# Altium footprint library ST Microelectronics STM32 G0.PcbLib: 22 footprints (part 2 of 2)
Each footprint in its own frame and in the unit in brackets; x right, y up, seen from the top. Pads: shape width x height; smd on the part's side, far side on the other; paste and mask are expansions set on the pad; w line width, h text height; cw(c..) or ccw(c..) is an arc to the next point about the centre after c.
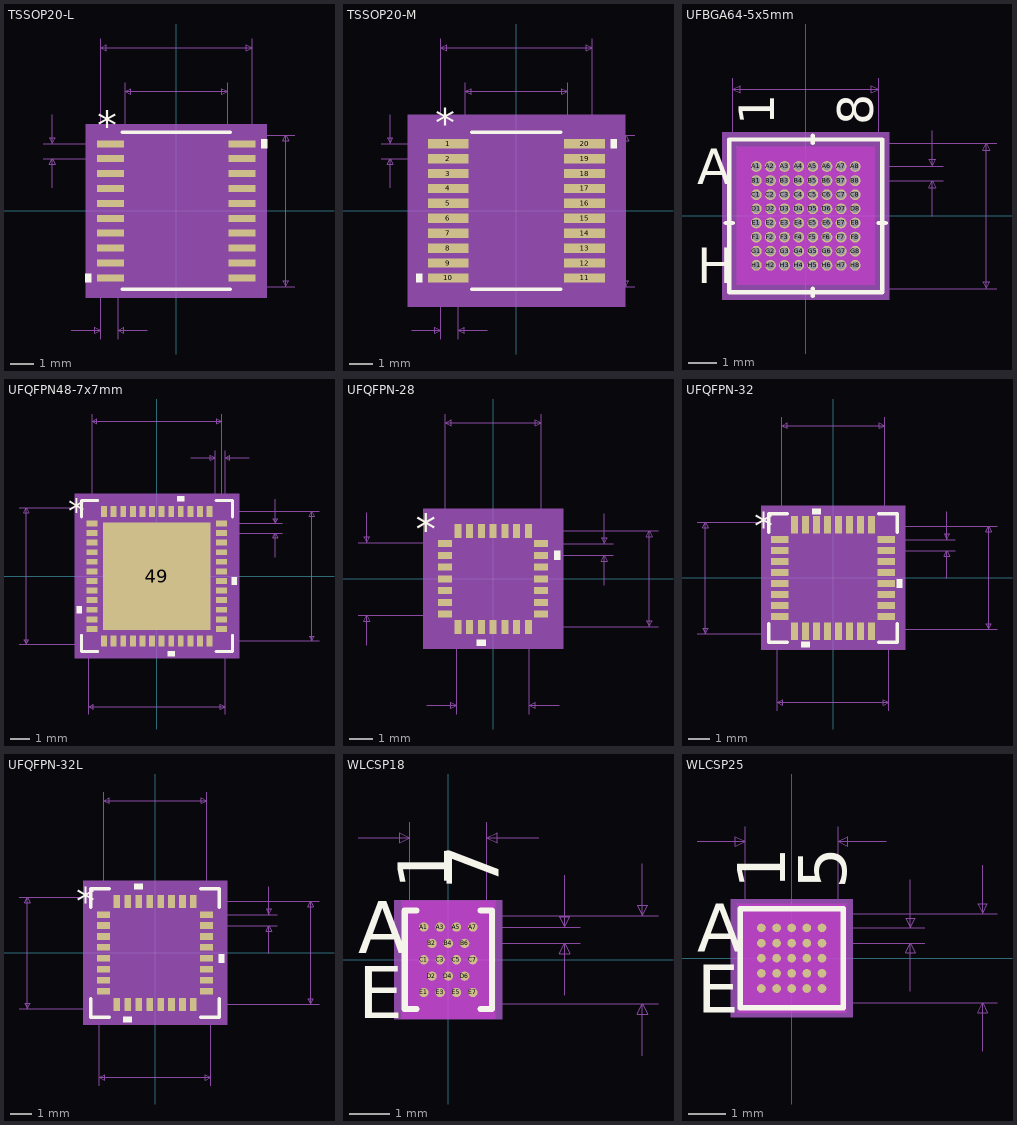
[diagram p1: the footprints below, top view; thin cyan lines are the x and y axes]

## TSSOP20-L [mil] "STM32 package, TSSOP20, 6.4 x 4.4mm"
pads (20):
  rect 46x12 smd paste+0 mask+0: 1(-113,115.16) 2(-113,89.57) 3(-113,63.98) 4(-113,38.39) 5(-113,12.8) 6(-113,-12.8) 7(-113,-38.39) 8(-113,-63.98) 9(-113,-89.57) 10(-113,-115.16) 11(113,-115.16) 12(113,-89.57) 13(113,-63.98) 14(113,-38.39) 15(113,-12.8) 16(113,12.8) 17(113,38.39) 18(113,63.98) 19(113,89.57) 20(113,115.16)
Top Overlay:
  region: 146,122.66 156,122.66 156,107.66 146,107.66
  region: -146,-107.66 -156,-107.66 -156,-122.66 -146,-122.66
  lines w6: -93,-135 93,-135 ; -93,135 93,135
  text "*" at -135.5,122.16 h50
Mechanical 5:
  region: 155,-149 -155,-149 -155,149 155,149
Mechanical 7:
  lines w1: -228,89.57 -113,89.57 ; -228,115.16 -113,115.16 ; -213,39.57 -213,89.57 ; -213,165.16 -213,115.16 ; -180,-205 -130,-205 ; -130,-220 -130,0 -130,295 ; -100,-220 -100,0 ; -88,0 -88,220 ; -50,-205 -100,-205 ; 0,-130 203,-130 ; 0,130 203,130 ; 88,0 88,220 ; 130,0 130,295 ; -213,89.57 -208,79.57 -218,79.57 -213,89.57 ; -213,115.16 -208,125.16 -218,125.16 -213,115.16 ; -130,-205 -140,-210 -140,-200 -130,-205 ; -130,280 -120,275 -120,285 -130,280 ; -130,280 130,280 ; -100,-205 -90,-210 -90,-200 -100,-205 ; -88,205 -78,200 -78,210 -88,205 ; -88,205 88,205 ; 88,205 78,200 78,210 88,205 ; 130,280 120,275 120,285 130,280 ; 188,-130 193,-120 183,-120 188,-130 ; 188,-130 188,130 ; 188,130 193,120 183,120 188,130
  text "0.03in/0.762mm" at -202.5,-250 h25
  text "0.026in/0.65mm" at -408,89.86 h25
  text "0.26in/6.604mm" at 208,-12.5 h25
  text "0.26in/6.604mm" at -87.5,300 h25
  text "0.176in/4.47mm" at -87.5,225 h25
  text "Alt 2 Padstyle: OX90Y60D30P" at -337.5,-630 h50
  text "Alt 1 Padstyle: OX60Y90D30P" at -337.5,-570 h50
  text "Pin One Padstyle: RX46Y12D0T" at -350,-390 h50
  text "Default Padstyle: RX46Y12D0T" at -350,-330 h50
Mechanical 13:
  lines w0: -12,130 ccw(c0,130) 12,130
  lines w1: -130,-121.16 -88,-121.16 -88,-109.16 -130,-109.16 -130,-121.16 ; -130,-95.57 -88,-95.57 -88,-83.57 -130,-83.57 -130,-95.57 ; -130,-69.98 -88,-69.98 -88,-57.98 -130,-57.98 -130,-69.98 ; -130,-44.39 -88,-44.39 -88,-32.39 -130,-32.39 -130,-44.39 ; -130,-18.8 -88,-18.8 -88,-6.8 -130,-6.8 -130,-18.8 ; -130,6.8 -88,6.8 -88,18.8 -130,18.8 -130,6.8 ; -130,32.39 -88,32.39 -88,44.39 -130,44.39 -130,32.39 ; -130,57.98 -88,57.98 -88,69.98 -130,69.98 -130,57.98 ; -130,83.57 -88,83.57 -88,95.57 -130,95.57 -130,83.57 ; -130,109.16 -88,109.16 -88,121.16 -130,121.16 -130,109.16 ; -88,-130 -88,130 88,130 88,-130 -88,-130 ; 88,-121.16 130,-121.16 130,-109.16 88,-109.16 88,-121.16 ; 88,-95.57 130,-95.57 130,-83.57 88,-83.57 88,-95.57 ; 88,-69.98 130,-69.98 130,-57.98 88,-57.98 88,-69.98 ; 88,-44.39 130,-44.39 130,-32.39 88,-32.39 88,-44.39 ; 88,-18.8 130,-18.8 130,-6.8 88,-6.8 88,-18.8 ; 88,6.8 130,6.8 130,18.8 88,18.8 88,6.8 ; 88,32.39 130,32.39 130,44.39 88,44.39 88,32.39 ; 88,57.98 130,57.98 130,69.98 88,69.98 88,57.98 ; 88,83.57 130,83.57 130,95.57 88,95.57 88,83.57 ; 88,109.16 130,109.16 130,121.16 88,121.16 88,109.16
  text "*" at -85.5,77 h50
Mechanical 15:
  region: -92,-125.16 -140,-125.16 -140,125.16 -92,125.16 -92,134 92,134 92,125.16 140,125.16 140,-125.16 92,-125.16 92,-134 -92,-134
  lines w6: -140,-125.16 -92,-125.16 -92,-134 92,-134 92,-125.16 140,-125.16 140,125.16 92,125.16 92,134 -92,134 -92,125.16 -140,125.16 -140,-125.16
3D body "TSSOP20-L.step": height 47.09, standoff 0, extent -129.99,-129.99 130.01,130.01
3D body: height 10, standoff 0, extent 0,0 10,10

## TSSOP20-M [mil] "STM32 package, TSSOP20, 6.4 x 4.4mm"
pads (20):
  rect 70x16 smd paste+0 mask+0: 1(-117,115.16) 2(-117,89.57) 3(-117,63.98) 4(-117,38.39) 5(-117,12.8) 6(-117,-12.8) 7(-117,-38.39) 8(-117,-63.98) 9(-117,-89.57) 10(-117,-115.16) 11(117,-115.16) 12(117,-89.57) 13(117,-63.98) 14(117,-38.39) 15(117,-12.8) 16(117,12.8) 17(117,38.39) 18(117,63.98) 19(117,89.57) 20(117,115.16)
Top Overlay:
  region: -162,-107.66 -172,-107.66 -172,-122.66 -162,-122.66
  region: 162,122.66 172,122.66 172,107.66 162,107.66
  lines w6: -76.4,-135 76.4,-135 ; -76.4,135 76.4,135
  text "*" at -139.5,126.16 h50
Mechanical 5:
  region: 187,-165 -187,-165 -187,165 187,165
Mechanical 7:
  lines w1: -232,89.57 -117,89.57 ; -232,115.16 -117,115.16 ; -217,39.57 -217,89.57 ; -217,165.16 -217,115.16 ; -180,-205 -130,-205 ; -130,-220 -130,0 -130,295 ; -100,-220 -100,0 ; -88,0 -88,220 ; -50,-205 -100,-205 ; 0,-130 203,-130 ; 0,130 203,130 ; 88,0 88,220 ; 130,0 130,295 ; -217,89.57 -222,79.57 -212,79.57 -217,89.57 ; -217,115.16 -222,125.16 -212,125.16 -217,115.16 ; -130,-205 -140,-200 -140,-210 -130,-205 ; -130,280 130,280 ; -130,280 -120,285 -120,275 -130,280 ; -100,-205 -90,-200 -90,-210 -100,-205 ; -88,205 88,205 ; -88,205 -78,210 -78,200 -88,205 ; 88,205 78,210 78,200 88,205 ; 130,280 120,285 120,275 130,280 ; 188,-130 188,130 ; 188,-130 183,-120 193,-120 188,-130 ; 188,130 183,120 193,120 188,130
  text "Default Padstyle: RX70Y16D0T" at -350,-330 h50
  text "Pin One Padstyle: RX70Y16D0T" at -350,-390 h50
  text "Alt 1 Padstyle: OX60Y90D30P" at -337.5,-570 h50
  text "Alt 2 Padstyle: OX90Y60D30P" at -337.5,-630 h50
  text "0.176in/4.47mm" at -87.5,225 h25
  text "0.26in/6.604mm" at -87.5,300 h25
  text "0.26in/6.604mm" at 208,-12.5 h25
  text "0.026in/0.65mm" at -412,89.86 h25
  text "0.03in/0.762mm" at -202.5,-250 h25
Mechanical 13:
  lines w0: -12,130 ccw(c0,130) 12,130
  lines w1: -130,-121.16 -130,-109.16 -88,-109.16 -88,-121.16 -130,-121.16 ; -130,-95.57 -130,-83.57 -88,-83.57 -88,-95.57 -130,-95.57 ; -130,-69.98 -130,-57.98 -88,-57.98 -88,-69.98 -130,-69.98 ; -130,-44.39 -130,-32.39 -88,-32.39 -88,-44.39 -130,-44.39 ; -130,-18.8 -130,-6.8 -88,-6.8 -88,-18.8 -130,-18.8 ; -130,6.8 -130,18.8 -88,18.8 -88,6.8 -130,6.8 ; -130,32.39 -130,44.39 -88,44.39 -88,32.39 -130,32.39 ; -130,57.98 -130,69.98 -88,69.98 -88,57.98 -130,57.98 ; -130,83.57 -130,95.57 -88,95.57 -88,83.57 -130,83.57 ; -130,109.16 -130,121.16 -88,121.16 -88,109.16 -130,109.16 ; -88,-130 88,-130 88,130 -88,130 -88,-130 ; 88,-121.16 88,-109.16 130,-109.16 130,-121.16 88,-121.16 ; 88,-95.57 88,-83.57 130,-83.57 130,-95.57 88,-95.57 ; 88,-69.98 88,-57.98 130,-57.98 130,-69.98 88,-69.98 ; 88,-44.39 88,-32.39 130,-32.39 130,-44.39 88,-44.39 ; 88,-18.8 88,-6.8 130,-6.8 130,-18.8 88,-18.8 ; 88,6.8 88,18.8 130,18.8 130,6.8 88,6.8 ; 88,32.39 88,44.39 130,44.39 130,32.39 88,32.39 ; 88,57.98 88,69.98 130,69.98 130,57.98 88,57.98 ; 88,83.57 88,95.57 130,95.57 130,83.57 88,83.57 ; 88,109.16 88,121.16 130,121.16 130,109.16 88,109.16
  text "*" at -85.5,77 h50
Mechanical 15:
  region: -108,-143.16 -172,-143.16 -172,143.16 -108,143.16 -108,150 108,150 108,143.16 172,143.16 172,-143.16 108,-143.16 108,-150 -108,-150
  lines w6: -172,-143.16 -172,143.16 -108,143.16 -108,150 108,150 108,143.16 172,143.16 172,-143.16 108,-143.16 108,-150 -108,-150 -108,-143.16 -172,-143.16
3D body: height 10, standoff 0, extent 0,0 10,10
3D body "TSSOP20-M.step": height 47.09, standoff 0, extent -129.99,-129.99 130.01,130.01

## UFBGA64-5x5mm [mil] "STM32 package, UFBGA64, 5 x 5mm"
pads (64):
  round 15 hole 11 mask+0: A1(-68.9,68.9) A2(-49.21,68.9) A3(-29.53,68.9) A4(-9.84,68.9) A5(9.84,68.9) A6(29.53,68.9) A7(49.21,68.9) A8(68.9,68.9) B1(-68.9,49.21) B2(-49.21,49.21) B3(-29.53,49.21) B4(-9.84,49.21) B5(9.84,49.21) B6(29.53,49.21) B7(49.21,49.21) B8(68.9,49.21) C1(-68.9,29.53) C2(-49.21,29.53) C3(-29.53,29.53) C4(-9.84,29.53) C5(9.84,29.53) C6(29.53,29.53) C7(49.21,29.53) C8(68.9,29.53) D1(-68.9,9.84) D2(-49.21,9.84) D3(-29.53,9.84) D4(-9.84,9.84) D5(9.84,9.84) D6(29.53,9.84) D7(49.21,9.84) D8(68.9,9.84) E1(-68.9,-9.84) E2(-49.21,-9.84) E3(-29.53,-9.84) E4(-9.84,-9.84) E5(9.84,-9.84) E6(29.53,-9.84) E7(49.21,-9.84) E8(68.9,-9.84) F1(-68.9,-29.53) F2(-49.21,-29.53) F3(-29.53,-29.53) F4(-9.84,-29.53) F5(9.84,-29.53) F6(29.53,-29.53) F7(49.21,-29.53) F8(68.9,-29.53) G1(-68.9,-49.21) G2(-49.21,-49.21) G3(-29.53,-49.21) G4(-9.84,-49.21) G5(9.84,-49.21) G6(29.53,-49.21) G7(49.21,-49.21) G8(68.9,-49.21) H1(-68.9,-68.9) H2(-49.21,-68.9) H3(-29.53,-68.9) H4(-9.84,-68.9) H5(9.84,-68.9) H6(29.53,-68.9) H7(49.21,-68.9) H8(68.9,-68.9)
Top Overlay:
  lines w6: -111.5,-9.84 -101.5,-9.84 ; 9.84,-111.5 9.84,-101.5 ; 9.84,101.5 9.84,111.5 ; 101.5,-9.84 111.5,-9.84 ; -106.5,-106.5 -106.5,106.5 106.5,106.5 106.5,-106.5 -106.5,-106.5
  text "8" at 93.9,126.5 h50
  text "1" at -43.9,126.5 h50
  text "H" at -151.5,-93.9 h50
  text "A" at -151.5,43.9 h50
Bottom Overlay:
  text "8" at 43.9,126.5 h50
  text "1" at -93.9,126.5 h50
  text "H" at -126.5,-93.9 h50
  text "A" at -126.5,43.9 h50
Keep-Out Layer:
  region: -96.24,-96.24 -96.24,96.24 96.24,96.24 96.24,-96.24
Mechanical 5:
  region: 116.5,-116.5 -116.5,-116.5 -116.5,116.5 116.5,116.5
Mechanical 7:
  lines w1: -101.5,0 -101.5,191.5 ; 0,-101.5 266.5,-101.5 ; 0,101.5 266.5,101.5 ; 68.9,49.21 191.5,49.21 ; 68.9,68.9 191.5,68.9 ; 101.5,0 101.5,191.5 ; 176.5,-0.79 176.5,49.21 ; 176.5,118.9 176.5,68.9 ; -101.5,176.5 -91.5,171.5 -91.5,181.5 -101.5,176.5 ; -101.5,176.5 101.5,176.5 ; 101.5,176.5 91.5,171.5 91.5,181.5 101.5,176.5 ; 176.5,49.21 181.5,39.21 171.5,39.21 176.5,49.21 ; 176.5,68.9 181.5,78.9 171.5,78.9 176.5,68.9 ; 251.5,-101.5 256.5,-91.5 246.5,-91.5 251.5,-101.5 ; 251.5,-101.5 251.5,101.5 ; 251.5,101.5 256.5,91.5 246.5,91.5 251.5,101.5
  text "0.203in/5.156mm" at 271.5,-12.5 h25
  text "0.203in/5.156mm" at -93.75,196.5 h25
  text "0.02in/0.5mm" at 196.5,46.56 h25
  text "Default Padstyle: EX15Y15D11P" at -362.5,-301.5 h50
Mechanical 13:
  lines w1: -101.5,91.66 -91.66,101.5 ; -101.5,-101.5 -101.5,101.5 101.5,101.5 101.5,-101.5 -101.5,-101.5
  text "8" at 93.9,126.5 h50
  text "1" at -43.9,126.5 h50
  text "H" at -151.5,-93.9 h50
  text "A" at -151.5,43.9 h50
Mechanical 15:
  region: 111.5,-111.5 -111.5,-111.5 -111.5,111.5 111.5,111.5
  lines w6: -111.5,-111.5 111.5,-111.5 111.5,111.5 -111.5,111.5 -111.5,-111.5
3D body "UFBGA64-5x5mm.step": height 24.09, standoff -0.02, extent -101.49,-101.49 101.5,101.5
3D body: height 10, standoff 0, extent 0,0 10,10

## UFQFPN48-7x7mm [mil] "STM32 package, UFQFPN48, 7 x 7mm"
pads (49):
  rect 22x12 smd: 1(-132.87,108.3) 2(-132.87,88.61) 3(-132.87,68.92) 4(-132.87,49.23) 5(-132.87,29.54) 6(-132.87,9.85) 7(-132.87,-9.85) 8(-132.87,-29.54) 9(-132.87,-49.23) 10(-132.87,-68.92) 11(-132.87,-88.61) 12(-132.87,-108.3) 25(132.87,-108.3) 26(132.87,-88.61) 27(132.87,-68.92) 28(132.87,-49.23) 29(132.87,-29.54) 30(132.87,-9.85) 31(132.87,9.85) 32(132.87,29.54) 33(132.87,49.23) 34(132.87,68.92) 35(132.87,88.61) 36(132.87,108.3)
  rect 12x22 smd: 13(-108.3,-132.87) 14(-88.61,-132.87) 15(-68.92,-132.87) 16(-49.23,-132.87) 17(-29.54,-132.87) 18(-9.85,-132.87) 19(9.85,-132.87) 20(29.54,-132.87) 21(49.23,-132.87) 22(68.92,-132.87) 23(88.61,-132.87) 24(108.3,-132.87) 37(108.3,132.87) 38(88.61,132.87) 39(68.92,132.87) 40(49.23,132.87) 41(29.54,132.87) 42(9.85,132.87) 43(-9.85,132.87) 44(-29.54,132.87) 45(-49.23,132.87) 46(-68.92,132.87) 47(-88.61,132.87) 48(-108.3,132.87)
  rect 220x220 smd paste-110: 49(0,0)
Top Overlay:
  region: 56.73,153.87 41.73,153.87 41.73,163.87 56.73,163.87
  region: 153.87,-2.35 163.87,-2.35 163.87,-17.34 153.87,-17.34
  region: 37.03,-153.87 22.04,-153.87 22.04,-163.87 37.03,-163.87
  region: -153.87,-61.41 -163.87,-61.41 -163.87,-76.42 -153.87,-76.42
  lines w6: -155,-121.21 -155,-155 -121.21,-155 ; -155,121.21 -155,155 -121.21,155 ; 121.21,-155 155,-155 155,-121.21 ; 121.21,155 155,155 155,121.21
  text "*" at -181.37,108.14 h50
Top Paste:
  drawing of 64 lines, arcs and shapes, not listed
Top Solder:
  drawing of 48 lines, arcs and shapes, not listed
Mechanical 5:
  region: 168.87,-168.87 -168.87,-168.87 -168.87,168.87 168.87,168.87
Mechanical 7:
  lines w1: -282.87,-140 140,-140 ; -282.87,140 140,140 140,-282.87 ; -140,-282.87 -140,140 ; -132.87,108.3 -132.87,332.87 ; 70,242.87 120,242.87 ; 108.3,-132.87 332.87,-132.87 ; 108.3,132.87 332.87,132.87 ; 120,108.3 120,257.87 ; 132.87,88.61 257.87,88.61 ; 132.87,332.87 132.87,108.3 257.87,108.3 ; 140,108.3 140,257.87 ; 190,242.87 140,242.87 ; 242.87,38.6 242.87,88.61 ; 242.87,158.29 242.87,108.3 ; -267.87,-140 -262.87,-130 -272.87,-130 -267.87,-140 ; -267.87,-140 -267.87,140 ; -267.87,140 -262.87,130 -272.87,130 -267.87,140 ; -140,-267.87 -130,-272.87 -130,-262.87 -140,-267.87 ; -140,-267.87 140,-267.87 ; -132.87,317.87 -122.87,312.87 -122.87,322.87 -132.87,317.87 ; -132.87,317.87 132.87,317.87 ; 120,242.87 110,237.87 110,247.87 120,242.87 ; 132.87,317.87 122.87,312.87 122.87,322.87 132.87,317.87 ; 140,-267.87 130,-272.87 130,-262.87 140,-267.87 ; 140,242.87 150,237.87 150,247.87 140,242.87 ; 242.87,88.61 247.87,78.61 237.87,78.61 242.87,88.61 ; 242.87,108.3 247.87,118.3 237.87,118.3 242.87,108.3 ; 317.87,-132.87 322.87,-122.87 312.87,-122.87 317.87,-132.87 ; 317.87,-132.87 317.87,132.87 ; 317.87,132.87 322.87,122.87 312.87,122.87 317.87,132.87
  text "0.28in/7.112mm" at -87.5,-312.87 h25
  text "0.28in/7.112mm" at -462.87,-12.5 h25
  text "0.266in/6.75mm" at 337.87,-12.5 h25
  text "0.266in/6.75mm" at -87.5,337.87 h25
  text "0.02in/0.508mm" at 42.5,262.87 h25
  text "0.02in/0.5mm" at 262.87,85.95 h25
  text "Alt 2 Padstyle: OX90Y60D30P" at -337.5,-632.87 h50
  text "Alt 1 Padstyle: OX60Y90D30P" at -337.5,-572.87 h50
  text "Heat Tab Padstyle: RX220Y220D0T" at -387.5,-452.87 h50
  text "Default Padstyle: RX12Y22D0T" at -350,-392.87 h50
Mechanical 13:
  lines w1: -140,90 -90,140 ; -140,-140 -140,140 140,140 140,-140 -140,-140 ; -140,-114.3 -140,-102.3 -140,-114.3 ; -140,-94.61 -140,-82.61 -140,-94.61 ; -140,-74.92 -140,-62.91 -140,-74.92 ; -140,-55.23 -140,-43.23 -140,-55.23 ; -140,-35.53 -140,-23.54 -140,-35.53 ; -140,-15.85 -140,-3.85 -140,-15.85 ; -140,3.85 -140,15.85 -140,3.85 ; -140,23.54 -140,35.53 -140,23.54 ; -140,43.23 -140,55.23 -140,43.23 ; -140,62.91 -140,74.92 -140,62.91 ; -140,82.61 -140,94.61 -140,82.61 ; -140,102.3 -140,114.3 -140,102.3 ; -114.3,-140 -102.3,-140 -114.3,-140 ; -114.3,140 -102.3,140 -114.3,140 ; -94.61,-140 -82.61,-140 -94.61,-140 ; -94.61,140 -82.61,140 -94.61,140 ; -74.92,-140 -62.91,-140 -74.92,-140 ; -74.92,140 -62.91,140 -74.92,140 ; -55.23,-140 -43.23,-140 -55.23,-140 ; -55.23,140 -43.23,140 -55.23,140 ; -35.53,-140 -23.54,-140 -35.53,-140 ; -35.53,140 -23.54,140 -35.53,140 ; -15.85,-140 -3.85,-140 -15.85,-140 ; -15.85,140 -3.85,140 -15.85,140 ; 3.85,-140 15.85,-140 3.85,-140 ; 3.85,140 15.85,140 3.85,140 ; 23.54,-140 35.53,-140 23.54,-140 ; 23.54,140 35.53,140 23.54,140 ; 43.23,-140 55.23,-140 43.23,-140 ; 43.23,140 55.23,140 43.23,140 ; 62.91,-140 74.92,-140 62.91,-140 ; 62.91,140 74.92,140 62.91,140 ; 82.61,-140 94.61,-140 82.61,-140 ; 82.61,140 94.61,140 82.61,140 ; 102.3,-140 114.3,-140 102.3,-140 ; 102.3,140 114.3,140 102.3,140 ; 140,-114.3 140,-102.3 140,-114.3 ; 140,-94.61 140,-82.61 140,-94.61 ; 140,-74.92 140,-62.91 140,-74.92 ; 140,-55.23 140,-43.23 140,-55.23 ; 140,-35.53 140,-23.54 140,-35.53 ; 140,-15.85 140,-3.85 140,-15.85 ; 140,3.85 140,15.85 140,3.85 ; 140,23.54 140,35.53 140,23.54 ; 140,43.23 140,55.23 140,43.23 ; 140,62.91 140,74.92 140,62.91 ; 140,82.61 140,94.61 140,82.61 ; 140,102.3 140,114.3 140,102.3
  text "*" at -124.37,93.14 h50
Mechanical 15:
  region: -128.29,-150 -150,-150 -150,-128.29 -148.87,-128.29 -148.87,128.29 -150,128.29 -150,150 -128.29,150 -128.29,148.87 128.29,148.87 128.29,150 150,150 150,128.29 148.87,128.29 148.87,-128.29 150,-128.29 150,-150 128.29,-150 128.29,-148.87 -128.29,-148.87
  lines w6: -150,-150 -128.29,-150 -128.29,-148.87 128.29,-148.87 128.29,-150 150,-150 150,-128.29 148.87,-128.29 148.87,128.29 150,128.29 150,150 128.29,150 128.29,148.87 -128.29,148.87 -128.29,150 -150,150 -150,128.29 -148.87,128.29 -148.87,-128.29 -150,-128.29 -150,-150
3D body "UFQFPN-48.stp": height 25.59, standoff 0, extent -139.76,-139.76 139.77,139.77

## UFQFPN-28 [mil] "STM32 package, UFQFPN28, 4 x 4mm"
pads (28):
  rect 23.62x11.81 smd paste-5.91 mask+0: 1(-80.5,59.1) 2(-80.5,39.4) 3(-80.5,19.7) 4(-80.5,0) 5(-80.5,-19.7) 6(-80.5,-39.4) 7(-80.5,-59.1) 15(80.5,-59.1) 16(80.5,-39.4) 17(80.5,-19.7) 18(80.5,0) 19(80.5,19.7) 20(80.5,39.4) 21(80.5,59.1)
  rect 11.81x23.62 smd paste-5.91 mask+0: 8(-59.1,-80.5) 9(-39.4,-80.5) 10(-19.7,-80.5) 11(0,-80.5) 12(19.7,-80.5) 13(39.4,-80.5) 14(59.1,-80.5) 22(59.1,80.5) 23(39.4,80.5) 24(19.7,80.5) 25(0,80.5) 26(-19.7,80.5) 27(-39.4,80.5) 28(-59.1,80.5)
Top Overlay:
  region: -12.2,-102.31 -27.2,-102.31 -27.2,-112.31 -12.2,-112.31
  region: 102.31,46.9 112.31,46.9 112.31,31.9 102.31,31.9
  text "*" at -129.81,58.95 h50
Top Paste:
  region: -68.69,65 -92.31,65 -92.31,53.2 -68.69,53.2
  region: -68.69,45.3 -92.31,45.3 -92.31,33.49 -68.69,33.49
  region: -68.69,25.61 -92.31,25.61 -92.31,13.79 -68.69,13.79
  region: -68.69,5.91 -92.31,5.91 -92.31,-5.91 -68.69,-5.91
  region: -68.69,-13.79 -92.31,-13.79 -92.31,-25.61 -68.69,-25.61
  region: -68.69,-33.49 -92.31,-33.49 -92.31,-45.3 -68.69,-45.3
  region: -68.69,-53.2 -92.31,-53.2 -92.31,-65 -68.69,-65
  region: -53.2,-68.69 -65,-68.69 -65,-92.31 -53.2,-92.31
  region: -33.49,-68.69 -45.3,-68.69 -45.3,-92.31 -33.49,-92.31
  region: -13.79,-68.69 -25.61,-68.69 -25.61,-92.31 -13.79,-92.31
  region: 5.91,-68.69 -5.91,-68.69 -5.91,-92.31 5.91,-92.31
  region: 25.61,-68.69 13.79,-68.69 13.79,-92.31 25.61,-92.31
  region: 45.3,-68.69 33.49,-68.69 33.49,-92.31 45.3,-92.31
  region: 65,-68.69 53.2,-68.69 53.2,-92.31 65,-92.31
  region: 92.31,-53.2 68.69,-53.2 68.69,-65 92.31,-65
  region: 92.31,-33.49 68.69,-33.49 68.69,-45.3 92.31,-45.3
  region: 92.31,-13.79 68.69,-13.79 68.69,-25.61 92.31,-25.61
  region: 92.31,5.91 68.69,5.91 68.69,-5.91 92.31,-5.91
  region: 92.31,25.61 68.69,25.61 68.69,13.79 92.31,13.79
  region: 92.31,45.3 68.69,45.3 68.69,33.49 92.31,33.49
  region: 92.31,65 68.69,65 68.69,53.2 92.31,53.2
  region: 65,92.31 53.2,92.31 53.2,68.69 65,68.69
  region: 45.3,92.31 33.49,92.31 33.49,68.69 45.3,68.69
  region: 25.61,92.31 13.79,92.31 13.79,68.69 25.61,68.69
  region: 5.91,92.31 -5.91,92.31 -5.91,68.69 5.91,68.69
  region: -13.79,92.31 -25.61,92.31 -25.61,68.69 -13.79,68.69
  region: -33.49,92.31 -45.3,92.31 -45.3,68.69 -33.49,68.69
  region: -53.2,92.31 -65,92.31 -65,68.69 -53.2,68.69
  region: -3.94,63.98 -63.98,63.98 -63.98,3.94 -3.94,3.94
  region: -3.94,-3.94 -63.98,-3.94 -63.98,-63.98 -3.94,-63.98
  region: 63.98,63.98 3.94,63.98 3.94,3.94 63.98,3.94
  region: 63.98,-3.94 3.94,-3.94 3.94,-63.98 63.98,-63.98
  region: -3.94,63.98 -63.98,63.98 -63.98,3.94 -3.94,3.94
  region: -3.94,-3.94 -63.98,-3.94 -63.98,-63.98 -3.94,-63.98
  region: 63.98,63.98 3.94,63.98 3.94,3.94 63.98,3.94
  region: 63.98,-3.94 3.94,-3.94 3.94,-63.98 63.98,-63.98
Top Solder:
  region: -68.69,65 -92.31,65 -92.31,53.2 -68.69,53.2
  region: -68.69,45.3 -92.31,45.3 -92.31,33.49 -68.69,33.49
  region: -68.69,25.61 -92.31,25.61 -92.31,13.79 -68.69,13.79
  region: -68.69,5.91 -92.31,5.91 -92.31,-5.91 -68.69,-5.91
  region: -68.69,-13.79 -92.31,-13.79 -92.31,-25.61 -68.69,-25.61
  region: -68.69,-33.49 -92.31,-33.49 -92.31,-45.3 -68.69,-45.3
  region: -68.69,-53.2 -92.31,-53.2 -92.31,-65 -68.69,-65
  region: -53.2,-68.69 -65,-68.69 -65,-92.31 -53.2,-92.31
  region: -33.49,-68.69 -45.3,-68.69 -45.3,-92.31 -33.49,-92.31
  region: -13.79,-68.69 -25.61,-68.69 -25.61,-92.31 -13.79,-92.31
  region: 5.91,-68.69 -5.91,-68.69 -5.91,-92.31 5.91,-92.31
  region: 25.61,-68.69 13.79,-68.69 13.79,-92.31 25.61,-92.31
  region: 45.3,-68.69 33.49,-68.69 33.49,-92.31 45.3,-92.31
  region: 65,-68.69 53.2,-68.69 53.2,-92.31 65,-92.31
  region: 92.31,-53.2 68.69,-53.2 68.69,-65 92.31,-65
  region: 92.31,-33.49 68.69,-33.49 68.69,-45.3 92.31,-45.3
  region: 92.31,-13.79 68.69,-13.79 68.69,-25.61 92.31,-25.61
  region: 92.31,5.91 68.69,5.91 68.69,-5.91 92.31,-5.91
  region: 92.31,25.61 68.69,25.61 68.69,13.79 92.31,13.79
  region: 92.31,45.3 68.69,45.3 68.69,33.49 92.31,33.49
  region: 92.31,65 68.69,65 68.69,53.2 92.31,53.2
  region: 65,92.31 53.2,92.31 53.2,68.69 65,68.69
  region: 45.3,92.31 33.49,92.31 33.49,68.69 45.3,68.69
  region: 25.61,92.31 13.79,92.31 13.79,68.69 25.61,68.69
  region: 5.91,92.31 -5.91,92.31 -5.91,68.69 5.91,68.69
  region: -13.79,92.31 -25.61,92.31 -25.61,68.69 -13.79,68.69
  region: -33.49,92.31 -45.3,92.31 -45.3,68.69 -33.49,68.69
  region: -53.2,92.31 -65,92.31 -65,68.69 -53.2,68.69
Mechanical 5:
  region: 117.31,-117.31 -117.31,-117.31 -117.31,117.31 117.31,117.31
Mechanical 7:
  lines w1: -226.4,-61 61,-61 ; -226.4,61 61,61 61,-226.4 ; -211.4,-111 -211.4,-61 ; -211.4,111 -211.4,61 ; -111,-211.4 -61,-211.4 ; -80.5,59.1 -80.5,276.4 ; -61,-226.4 -61,61 ; 59.1,-80.5 276.4,-80.5 ; 59.1,80.5 276.4,80.5 ; 80.5,39.4 201.4,39.4 ; 80.5,276.4 80.5,59.1 201.4,59.1 ; 111,-211.4 61,-211.4 ; 186.4,-10.6 186.4,39.4 ; 186.4,109.1 186.4,59.1 ; -211.4,-61 -216.4,-71 -206.4,-71 -211.4,-61 ; -211.4,61 -216.4,71 -206.4,71 -211.4,61 ; -80.5,261.4 80.5,261.4 ; -80.5,261.4 -70.5,266.4 -70.5,256.4 -80.5,261.4 ; -61,-211.4 -71,-206.4 -71,-216.4 -61,-211.4 ; 61,-211.4 71,-206.4 71,-216.4 61,-211.4 ; 80.5,261.4 70.5,266.4 70.5,256.4 80.5,261.4 ; 186.4,39.4 181.4,29.4 191.4,29.4 186.4,39.4 ; 186.4,59.1 181.4,69.1 191.4,69.1 186.4,59.1 ; 261.4,-80.5 261.4,80.5 ; 261.4,-80.5 256.4,-70.5 266.4,-70.5 261.4,-80.5 ; 261.4,80.5 256.4,70.5 266.4,70.5 261.4,80.5
  text "Default Padstyle: RX11p81Y23p62D0T" at -425,-336.4 h50
  text "Alt 1 Padstyle: OX60Y90D30P" at -337.5,-516.4 h50
  text "Alt 2 Padstyle: OX90Y60D30P" at -337.5,-576.4 h50
  text "0.02in/0.5mm" at 206.4,36.75 h25
  text "0.161in/4.089mm" at -93.75,281.4 h25
  text "0.161in/4.089mm" at 281.4,-12.5 h25
  text "0.122in/3.099mm" at -418.9,-12.5 h25
  text "0.122in/3.099mm" at -93.75,-256.4 h25
Mechanical 13:
  lines w1: -61,11 -11,61 ; -61,-61 61,-61 61,61 -61,61 -61,-61
  text "*" at -71.19,43.95 h50
Mechanical 15:
  region: -75,-71 -71,-71 -71,-75 -102.31,-75 -102.31,75 -71,75 -71,71 -75,71 -75,102.31 75,102.31 75,71 71,71 71,75 102.31,75 102.31,-75 71,-75 71,-71 75,-71 75,-102.31 -75,-102.31
  lines w6: -102.31,-75 -71,-75 -71,-71 -75,-71 -75,-102.31 75,-102.31 75,-71 71,-71 71,-75 102.31,-75 102.31,75 71,75 71,71 75,71 75,102.31 -75,102.31 -75,71 -71,71 -71,75 -102.31,75 -102.31,-75
3D body: height 10, standoff 0, extent 0,0 10,10
3D body "UFQFPN-28.step": height 22.09, standoff 0, extent -68.7,-68.69 68.71,68.71

## UFQFPN-32 [mm] "STM32 package, UFQFPN32, 5 x 5mm"
pads (32):
  rect 0.8x0.32 smd paste-0.15 mask+0: 1(-2.425,1.75) 2(-2.425,1.25) 3(-2.425,0.75) 4(-2.425,0.25) 5(-2.425,-0.25) 6(-2.425,-0.75) 7(-2.425,-1.25) 8(-2.425,-1.75) 17(2.425,-1.75) 18(2.425,-1.25) 19(2.425,-0.75) 20(2.425,-0.25) 21(2.425,0.25) 22(2.425,0.75) 23(2.425,1.25) 24(2.425,1.75)
  rect 0.32x0.8 smd paste-0.15 mask+0: 9(-1.75,-2.425) 10(-1.25,-2.425) 11(-0.75,-2.425) 12(-0.25,-2.425) 13(0.25,-2.425) 14(0.75,-2.425) 15(1.25,-2.425) 16(1.75,-2.425) 25(1.75,2.425) 26(1.25,2.425) 27(0.75,2.425) 28(0.25,2.425) 29(-0.25,2.425) 30(-0.75,2.425) 31(-1.25,2.425) 32(-1.75,2.425)
Top Overlay:
  region: -0.56,2.904 -0.941,2.904 -0.941,3.158 -0.56,3.158
  region: 2.904,-0.059 3.158,-0.059 3.158,-0.44 2.904,-0.44
  region: -1.06,-2.904 -1.441,-2.904 -1.441,-3.158 -1.06,-3.158
  lines w0.152: -2.931,-2.078 -2.931,-2.931 -2.078,-2.931 ; -2.931,2.078 -2.931,2.931 -2.078,2.931 ; 2.078,-2.931 2.931,-2.931 2.931,-2.078 ; 2.078,2.931 2.931,2.931 2.931,2.078
  text "*" at -3.602,1.746 h1.27
Top Paste:
  region: -1.6,2.65 -1.9,2.65 -1.9,2.05 -1.6,2.05
  region: -1.1,2.65 -1.4,2.65 -1.4,2.05 -1.1,2.05
  region: -0.6,2.65 -0.9,2.65 -0.9,2.05 -0.6,2.05
  region: -0.1,2.65 -0.4,2.65 -0.4,2.05 -0.1,2.05
  region: 0.4,2.65 0.1,2.65 0.1,2.05 0.4,2.05
  region: 0.9,2.65 0.6,2.65 0.6,2.05 0.9,2.05
  region: 1.4,2.65 1.1,2.65 1.1,2.05 1.4,2.05
  region: 1.9,2.65 1.6,2.65 1.6,2.05 1.9,2.05
  region: 2.65,1.9 2.05,1.9 2.05,1.6 2.65,1.6
  region: 2.65,1.4 2.05,1.4 2.05,1.1 2.65,1.1
  region: 2.65,0.9 2.05,0.9 2.05,0.6 2.65,0.6
  region: 2.65,0.4 2.05,0.4 2.05,0.1 2.65,0.1
  region: 2.65,-0.1 2.05,-0.1 2.05,-0.4 2.65,-0.4
  region: 2.65,-0.6 2.05,-0.6 2.05,-0.9 2.65,-0.9
  region: 2.65,-1.1 2.05,-1.1 2.05,-1.4 2.65,-1.4
  region: 2.65,-1.6 2.05,-1.6 2.05,-1.9 2.65,-1.9
  region: 1.9,-2.05 1.6,-2.05 1.6,-2.65 1.9,-2.65
  region: 1.4,-2.05 1.1,-2.05 1.1,-2.65 1.4,-2.65
  region: 0.9,-2.05 0.6,-2.05 0.6,-2.65 0.9,-2.65
  region: 0.4,-2.05 0.1,-2.05 0.1,-2.65 0.4,-2.65
  region: -0.1,-2.05 -0.4,-2.05 -0.4,-2.65 -0.1,-2.65
  region: -0.6,-2.05 -0.9,-2.05 -0.9,-2.65 -0.6,-2.65
  region: -1.1,-2.05 -1.4,-2.05 -1.4,-2.65 -1.1,-2.65
  region: -1.6,-2.05 -1.9,-2.05 -1.9,-2.65 -1.6,-2.65
  region: -2.05,-1.6 -2.65,-1.6 -2.65,-1.9 -2.05,-1.9
  region: -2.05,-1.1 -2.65,-1.1 -2.65,-1.4 -2.05,-1.4
  region: -2.05,-0.6 -2.65,-0.6 -2.65,-0.9 -2.05,-0.9
  region: -2.05,-0.1 -2.65,-0.1 -2.65,-0.4 -2.05,-0.4
  region: -2.05,0.4 -2.65,0.4 -2.65,0.1 -2.05,0.1
  region: -2.05,0.9 -2.65,0.9 -2.65,0.6 -2.05,0.6
  region: -2.05,1.4 -2.65,1.4 -2.65,1.1 -2.05,1.1
  region: -2.05,1.9 -2.65,1.9 -2.65,1.6 -2.05,1.6
Top Solder:
  region: -1.6,2.65 -1.9,2.65 -1.9,2.05 -1.6,2.05
  region: -1.1,2.65 -1.4,2.65 -1.4,2.05 -1.1,2.05
  region: -0.6,2.65 -0.9,2.65 -0.9,2.05 -0.6,2.05
  region: -0.1,2.65 -0.4,2.65 -0.4,2.05 -0.1,2.05
  region: 0.4,2.65 0.1,2.65 0.1,2.05 0.4,2.05
  region: 0.9,2.65 0.6,2.65 0.6,2.05 0.9,2.05
  region: 1.4,2.65 1.1,2.65 1.1,2.05 1.4,2.05
  region: 1.9,2.65 1.6,2.65 1.6,2.05 1.9,2.05
  region: 2.65,1.9 2.05,1.9 2.05,1.6 2.65,1.6
  region: 2.65,1.4 2.05,1.4 2.05,1.1 2.65,1.1
  region: 2.65,0.9 2.05,0.9 2.05,0.6 2.65,0.6
  region: 2.65,0.4 2.05,0.4 2.05,0.1 2.65,0.1
  region: 2.65,-0.1 2.05,-0.1 2.05,-0.4 2.65,-0.4
  region: 2.65,-0.6 2.05,-0.6 2.05,-0.9 2.65,-0.9
  region: 2.65,-1.1 2.05,-1.1 2.05,-1.4 2.65,-1.4
  region: 2.65,-1.6 2.05,-1.6 2.05,-1.9 2.65,-1.9
  region: 1.9,-2.05 1.6,-2.05 1.6,-2.65 1.9,-2.65
  region: 1.4,-2.05 1.1,-2.05 1.1,-2.65 1.4,-2.65
  region: 0.9,-2.05 0.6,-2.05 0.6,-2.65 0.9,-2.65
  region: 0.4,-2.05 0.1,-2.05 0.1,-2.65 0.4,-2.65
  region: -0.1,-2.05 -0.4,-2.05 -0.4,-2.65 -0.1,-2.65
  region: -0.6,-2.05 -0.9,-2.05 -0.9,-2.65 -0.6,-2.65
  region: -1.1,-2.05 -1.4,-2.05 -1.4,-2.65 -1.1,-2.65
  region: -1.6,-2.05 -1.9,-2.05 -1.9,-2.65 -1.6,-2.65
  region: -2.05,-1.6 -2.65,-1.6 -2.65,-1.9 -2.05,-1.9
  region: -2.05,-1.1 -2.65,-1.1 -2.65,-1.4 -2.05,-1.4
  region: -2.05,-0.6 -2.65,-0.6 -2.65,-0.9 -2.05,-0.9
  region: -2.05,-0.1 -2.65,-0.1 -2.65,-0.4 -2.05,-0.4
  region: -2.05,0.4 -2.65,0.4 -2.65,0.1 -2.05,0.1
  region: -2.05,0.9 -2.65,0.9 -2.65,0.6 -2.05,0.6
  region: -2.05,1.4 -2.65,1.4 -2.65,1.1 -2.05,1.1
  region: -2.05,1.9 -2.65,1.9 -2.65,1.6 -2.05,1.6
Mechanical 5:
  region: 3.285,-3.285 -3.285,-3.285 -3.285,3.285 3.285,3.285
Mechanical 7:
  lines w0.025: -6.206,-2.55 2.55,-2.55 ; -6.206,2.55 2.55,2.55 2.55,-6.056 ; -2.55,-6.056 -2.55,2.55 ; -2.35,1.75 -2.35,7.326 ; 1.75,-2.35 7.476,-2.35 ; 1.75,2.35 7.476,2.35 ; 2.35,1.25 5.571,1.25 ; 2.35,7.326 2.35,1.75 5.571,1.75 ; 5.19,-0.02 5.19,1.25 ; 5.19,3.02 5.19,1.75 ; -5.825,-2.55 -5.698,-2.296 -5.952,-2.296 -5.825,-2.55 ; -5.825,-2.55 -5.825,2.55 ; -5.825,2.55 -5.698,2.296 -5.952,2.296 -5.825,2.55 ; -2.55,-5.675 -2.296,-5.802 -2.296,-5.548 -2.55,-5.675 ; -2.55,-5.675 2.55,-5.675 ; -2.35,6.945 -2.096,6.818 -2.096,7.072 -2.35,6.945 ; -2.35,6.945 2.35,6.945 ; 2.35,6.945 2.096,6.818 2.096,7.072 2.35,6.945 ; 2.55,-5.675 2.296,-5.802 2.296,-5.548 2.55,-5.675 ; 5.19,1.25 5.317,0.996 5.063,0.996 5.19,1.25 ; 5.19,1.75 5.317,2.004 5.063,2.004 5.19,1.75 ; 7.095,-2.35 7.222,-2.096 6.968,-2.096 7.095,-2.35 ; 7.095,-2.35 7.095,2.35 ; 7.095,2.35 7.222,2.096 6.968,2.096 7.095,2.35
  text "0.201in/5.1mm" at -2.064,-6.818 h0.64
  text "0.201in/5.1mm" at -10.46,-0.318 h0.64
  text "0.185in/4.7mm" at 7.603,-0.318 h0.64
  text "0.185in/4.7mm" at -2.064,7.453 h0.64
  text "0.02in/0.5mm" at 5.698,1.182 h0.64
  text "Alt 2 Padstyle: OX60Y90D30P" at -8.572,-14.946 h1.27
  text "Alt 1 Padstyle: OX90Y60D30P" at -8.572,-13.422 h1.27
  text "Default Padstyle: RX23p62Y11p81D0T" at -10.795,-8.85 h1.27
Mechanical 13:
  lines w0.025: -2.55,1.28 -1.28,2.55 ; -2.55,-2.55 -2.55,2.55 2.55,2.55 2.55,-2.55 -2.55,-2.55
  text "*" at -2.114,1.365 h1.27
Mechanical 15:
  region: -2.154,-2.804 -2.804,-2.804 -2.804,-2.154 -2.904,-2.154 -2.904,2.154 -2.804,2.154 -2.804,2.804 -2.154,2.804 -2.154,2.904 2.154,2.904 2.154,2.804 2.804,2.804 2.804,2.154 2.904,2.154 2.904,-2.154 2.804,-2.154 2.804,-2.804 2.154,-2.804 2.154,-2.904 -2.154,-2.904
  lines w0.152: -2.904,-2.154 -2.904,2.154 -2.804,2.154 -2.804,2.804 -2.154,2.804 -2.154,2.904 2.154,2.904 2.154,2.804 2.804,2.804 2.804,2.154 2.904,2.154 2.904,-2.154 2.804,-2.154 2.804,-2.804 2.154,-2.804 2.154,-2.904 -2.154,-2.904 -2.154,-2.804 -2.804,-2.804 -2.804,-2.154 -2.904,-2.154
3D body: height 0.25, standoff 0, extent 0,0 0.254,0.254
3D body "UFQFPN-32.step": height 1.4, standoff 0, extent -2.601,-2.601 2.601,2.601

## UFQFPN-32L [mm] "STM32 package, UFQFPN32, 5 x 5mm"
pads (32):
  rect 0.6x0.3 smd paste-0.15 mask+0: 1(-2.35,1.75) 2(-2.35,1.25) 3(-2.35,0.75) 4(-2.35,0.25) 5(-2.35,-0.25) 6(-2.35,-0.75) 7(-2.35,-1.25) 8(-2.35,-1.75) 17(2.35,-1.75) 18(2.35,-1.25) 19(2.35,-0.75) 20(2.35,-0.25) 21(2.35,0.25) 22(2.35,0.75) 23(2.35,1.25) 24(2.35,1.75)
  rect 0.3x0.6 smd paste-0.15 mask+0: 9(-1.75,-2.35) 10(-1.25,-2.35) 11(-0.75,-2.35) 12(-0.25,-2.35) 13(0.25,-2.35) 14(0.75,-2.35) 15(1.25,-2.35) 16(1.75,-2.35) 25(1.75,2.35) 26(1.25,2.35) 27(0.75,2.35) 28(0.25,2.35) 29(-0.25,2.35) 30(-0.75,2.35) 31(-1.25,2.35) 32(-1.75,2.35)
Top Overlay:
  region: -0.56,2.904 -0.941,2.904 -0.941,3.158 -0.56,3.158
  region: 2.904,-0.059 3.158,-0.059 3.158,-0.44 2.904,-0.44
  region: -1.06,-2.904 -1.441,-2.904 -1.441,-3.158 -1.06,-3.158
  lines w0.152: -2.931,-2.078 -2.931,-2.931 -2.078,-2.931 ; -2.931,2.078 -2.931,2.931 -2.078,2.931 ; 2.078,-2.931 2.931,-2.931 2.931,-2.078 ; 2.078,2.931 2.931,2.931 2.931,2.078
  text "*" at -3.602,1.746 h1.27
Top Paste:
  region: -1.6,2.65 -1.9,2.65 -1.9,2.05 -1.6,2.05
  region: -1.1,2.65 -1.4,2.65 -1.4,2.05 -1.1,2.05
  region: -0.6,2.65 -0.9,2.65 -0.9,2.05 -0.6,2.05
  region: -0.1,2.65 -0.4,2.65 -0.4,2.05 -0.1,2.05
  region: 0.4,2.65 0.1,2.65 0.1,2.05 0.4,2.05
  region: 0.9,2.65 0.6,2.65 0.6,2.05 0.9,2.05
  region: 1.4,2.65 1.1,2.65 1.1,2.05 1.4,2.05
  region: 1.9,2.65 1.6,2.65 1.6,2.05 1.9,2.05
  region: 2.65,1.9 2.05,1.9 2.05,1.6 2.65,1.6
  region: 2.65,1.4 2.05,1.4 2.05,1.1 2.65,1.1
  region: 2.65,0.9 2.05,0.9 2.05,0.6 2.65,0.6
  region: 2.65,0.4 2.05,0.4 2.05,0.1 2.65,0.1
  region: 2.65,-0.1 2.05,-0.1 2.05,-0.4 2.65,-0.4
  region: 2.65,-0.6 2.05,-0.6 2.05,-0.9 2.65,-0.9
  region: 2.65,-1.1 2.05,-1.1 2.05,-1.4 2.65,-1.4
  region: 2.65,-1.6 2.05,-1.6 2.05,-1.9 2.65,-1.9
  region: 1.9,-2.05 1.6,-2.05 1.6,-2.65 1.9,-2.65
  region: 1.4,-2.05 1.1,-2.05 1.1,-2.65 1.4,-2.65
  region: 0.9,-2.05 0.6,-2.05 0.6,-2.65 0.9,-2.65
  region: 0.4,-2.05 0.1,-2.05 0.1,-2.65 0.4,-2.65
  region: -0.1,-2.05 -0.4,-2.05 -0.4,-2.65 -0.1,-2.65
  region: -0.6,-2.05 -0.9,-2.05 -0.9,-2.65 -0.6,-2.65
  region: -1.1,-2.05 -1.4,-2.05 -1.4,-2.65 -1.1,-2.65
  region: -1.6,-2.05 -1.9,-2.05 -1.9,-2.65 -1.6,-2.65
  region: -2.05,-1.6 -2.65,-1.6 -2.65,-1.9 -2.05,-1.9
  region: -2.05,-1.1 -2.65,-1.1 -2.65,-1.4 -2.05,-1.4
  region: -2.05,-0.6 -2.65,-0.6 -2.65,-0.9 -2.05,-0.9
  region: -2.05,-0.1 -2.65,-0.1 -2.65,-0.4 -2.05,-0.4
  region: -2.05,0.4 -2.65,0.4 -2.65,0.1 -2.05,0.1
  region: -2.05,0.9 -2.65,0.9 -2.65,0.6 -2.05,0.6
  region: -2.05,1.4 -2.65,1.4 -2.65,1.1 -2.05,1.1
  region: -2.05,1.9 -2.65,1.9 -2.65,1.6 -2.05,1.6
Top Solder:
  region: -1.6,2.65 -1.9,2.65 -1.9,2.05 -1.6,2.05
  region: -1.1,2.65 -1.4,2.65 -1.4,2.05 -1.1,2.05
  region: -0.6,2.65 -0.9,2.65 -0.9,2.05 -0.6,2.05
  region: -0.1,2.65 -0.4,2.65 -0.4,2.05 -0.1,2.05
  region: 0.4,2.65 0.1,2.65 0.1,2.05 0.4,2.05
  region: 0.9,2.65 0.6,2.65 0.6,2.05 0.9,2.05
  region: 1.4,2.65 1.1,2.65 1.1,2.05 1.4,2.05
  region: 1.9,2.65 1.6,2.65 1.6,2.05 1.9,2.05
  region: 2.65,1.9 2.05,1.9 2.05,1.6 2.65,1.6
  region: 2.65,1.4 2.05,1.4 2.05,1.1 2.65,1.1
  region: 2.65,0.9 2.05,0.9 2.05,0.6 2.65,0.6
  region: 2.65,0.4 2.05,0.4 2.05,0.1 2.65,0.1
  region: 2.65,-0.1 2.05,-0.1 2.05,-0.4 2.65,-0.4
  region: 2.65,-0.6 2.05,-0.6 2.05,-0.9 2.65,-0.9
  region: 2.65,-1.1 2.05,-1.1 2.05,-1.4 2.65,-1.4
  region: 2.65,-1.6 2.05,-1.6 2.05,-1.9 2.65,-1.9
  region: 1.9,-2.05 1.6,-2.05 1.6,-2.65 1.9,-2.65
  region: 1.4,-2.05 1.1,-2.05 1.1,-2.65 1.4,-2.65
  region: 0.9,-2.05 0.6,-2.05 0.6,-2.65 0.9,-2.65
  region: 0.4,-2.05 0.1,-2.05 0.1,-2.65 0.4,-2.65
  region: -0.1,-2.05 -0.4,-2.05 -0.4,-2.65 -0.1,-2.65
  region: -0.6,-2.05 -0.9,-2.05 -0.9,-2.65 -0.6,-2.65
  region: -1.1,-2.05 -1.4,-2.05 -1.4,-2.65 -1.1,-2.65
  region: -1.6,-2.05 -1.9,-2.05 -1.9,-2.65 -1.6,-2.65
  region: -2.05,-1.6 -2.65,-1.6 -2.65,-1.9 -2.05,-1.9
  region: -2.05,-1.1 -2.65,-1.1 -2.65,-1.4 -2.05,-1.4
  region: -2.05,-0.6 -2.65,-0.6 -2.65,-0.9 -2.05,-0.9
  region: -2.05,-0.1 -2.65,-0.1 -2.65,-0.4 -2.05,-0.4
  region: -2.05,0.4 -2.65,0.4 -2.65,0.1 -2.05,0.1
  region: -2.05,0.9 -2.65,0.9 -2.65,0.6 -2.05,0.6
  region: -2.05,1.4 -2.65,1.4 -2.65,1.1 -2.05,1.1
  region: -2.05,1.9 -2.65,1.9 -2.65,1.6 -2.05,1.6
Mechanical 5:
  region: 3.285,-3.285 -3.285,-3.285 -3.285,3.285 3.285,3.285
Mechanical 7:
  lines w0.025: -6.206,-2.55 2.55,-2.55 ; -6.206,2.55 2.55,2.55 2.55,-6.056 ; -2.55,-6.056 -2.55,2.55 ; -2.35,1.75 -2.35,7.326 ; 1.75,-2.35 7.476,-2.35 ; 1.75,2.35 7.476,2.35 ; 2.35,1.25 5.571,1.25 ; 2.35,7.326 2.35,1.75 5.571,1.75 ; 5.19,-0.02 5.19,1.25 ; 5.19,3.02 5.19,1.75 ; -5.825,-2.55 -5.698,-2.296 -5.952,-2.296 -5.825,-2.55 ; -5.825,-2.55 -5.825,2.55 ; -5.825,2.55 -5.698,2.296 -5.952,2.296 -5.825,2.55 ; -2.55,-5.675 -2.296,-5.802 -2.296,-5.548 -2.55,-5.675 ; -2.55,-5.675 2.55,-5.675 ; -2.35,6.945 -2.096,6.818 -2.096,7.072 -2.35,6.945 ; -2.35,6.945 2.35,6.945 ; 2.35,6.945 2.096,6.818 2.096,7.072 2.35,6.945 ; 2.55,-5.675 2.296,-5.802 2.296,-5.548 2.55,-5.675 ; 5.19,1.25 5.317,0.996 5.063,0.996 5.19,1.25 ; 5.19,1.75 5.317,2.004 5.063,2.004 5.19,1.75 ; 7.095,-2.35 7.222,-2.096 6.968,-2.096 7.095,-2.35 ; 7.095,-2.35 7.095,2.35 ; 7.095,2.35 7.222,2.096 6.968,2.096 7.095,2.35
  text "0.201in/5.1mm" at -2.064,-6.818 h0.64
  text "0.201in/5.1mm" at -10.46,-0.318 h0.64
  text "0.185in/4.7mm" at 7.603,-0.318 h0.64
  text "0.185in/4.7mm" at -2.064,7.453 h0.64
  text "0.02in/0.5mm" at 5.698,1.182 h0.64
  text "Alt 2 Padstyle: OX60Y90D30P" at -8.572,-14.946 h1.27
  text "Alt 1 Padstyle: OX90Y60D30P" at -8.572,-13.422 h1.27
  text "Default Padstyle: RX23p62Y11p81D0T" at -10.795,-8.85 h1.27
Mechanical 13:
  lines w0.025: -2.55,1.28 -1.28,2.55 ; -2.55,-2.55 -2.55,2.55 2.55,2.55 2.55,-2.55 -2.55,-2.55
  text "*" at -2.114,1.365 h1.27
Mechanical 15:
  region: -2.154,-2.804 -2.804,-2.804 -2.804,-2.154 -2.904,-2.154 -2.904,2.154 -2.804,2.154 -2.804,2.804 -2.154,2.804 -2.154,2.904 2.154,2.904 2.154,2.804 2.804,2.804 2.804,2.154 2.904,2.154 2.904,-2.154 2.804,-2.154 2.804,-2.804 2.154,-2.804 2.154,-2.904 -2.154,-2.904
  lines w0.152: -2.904,-2.154 -2.904,2.154 -2.804,2.154 -2.804,2.804 -2.154,2.804 -2.154,2.904 2.154,2.904 2.154,2.804 2.804,2.804 2.804,2.154 2.904,2.154 2.904,-2.154 2.804,-2.154 2.804,-2.804 2.154,-2.804 2.154,-2.904 -2.154,-2.904 -2.154,-2.804 -2.804,-2.804 -2.804,-2.154 -2.904,-2.154
3D body: height 0.25, standoff 0, extent 0,0 0.254,0.254
3D body "UFQFPN-32.step": height 1.4, standoff 0, extent -2.601,-2.601 2.601,2.601

## WLCSP18 [mil] "STM32 package, WLCSP18, 1.86 x 2.14mm"
pads (18):
  round 9 smd paste+0 mask+0: A1(-23.62,31.5) A3(-7.87,31.5) A5(7.87,31.5) A7(23.62,31.5) B2(-15.75,15.75) B4(0,15.75) B6(15.75,15.75) C1(-23.62,0) C3(-7.87,0) C5(7.87,0) C7(23.62,0) D2(-15.75,-15.75) D4(0,-15.75) D6(15.75,-15.75) E1(-23.62,-31.5) E3(-7.87,-31.5) E5(7.87,-31.5) E7(23.62,-31.5)
Top Overlay:
  lines w6: -30.95,-47.5 -42,-47.5 -42,47.5 -30.95,47.5 ; 30.95,-47.5 42,-47.5 42,47.5 30.95,47.5
  text "7" at 48.62,67.5 h50
  text "1" at 1.38,67.5 h50
  text "E" at -87,-56.5 h50
  text "A" at -87,6.5 h50
Bottom Overlay:
  text "7" at -1.38,67.5 h50
  text "1" at -48.62,67.5 h50
  text "E" at -62,-56.5 h50
  text "A" at -62,6.5 h50
Keep-Out Layer:
  region: -45.06,-56.87 -45.06,56.87 45.06,56.87 45.06,-56.87
Mechanical 5:
  region: 52,-57.5 -52,-57.5 -52,57.5 52,57.5
Mechanical 7:
  lines w1: -87,117.5 -37,117.5 ; -37,0 -37,132.5 ; 0,-42.5 202,-42.5 ; 0,42.5 202,42.5 ; 23.62,15.75 127,15.75 ; 23.62,31.5 127,31.5 ; 37,0 37,132.5 ; 87,117.5 37,117.5 ; 112,-34.25 112,15.75 ; 112,81.5 112,31.5 ; 187,-92.5 187,-42.5 ; 187,92.5 187,42.5 ; -37,117.5 -47,112.5 -47,122.5 -37,117.5 ; 37,117.5 47,112.5 47,122.5 37,117.5 ; 112,15.75 117,5.75 107,5.75 112,15.75 ; 112,31.5 117,41.5 107,41.5 112,31.5 ; 187,-42.5 192,-52.5 182,-52.5 187,-42.5 ; 187,42.5 192,52.5 182,52.5 187,42.5
  text "0.085in/2.159mm" at 207,-12.5 h25
  text "0.074in/1.88mm" at -87.5,137.5 h25
  text "0.016in/0.4mm" at 132,11.12 h25
  text "Default Padstyle: EX9Y9D0T" at -325,-242.5 h50
Mechanical 13:
  lines w1: -37,34.63 -33.06,42.5 ; -37,-42.5 -37,42.5 37,42.5 37,-42.5 -37,-42.5
  text "7" at 48.62,67.5 h50
  text "1" at 1.38,67.5 h50
  text "E" at -87,-56.5 h50
  text "A" at -87,6.5 h50
Mechanical 15:
  region: 47,-52.5 -47,-52.5 -47,52.5 47,52.5
  lines w6: -47,-52.5 47,-52.5 47,52.5 -47,52.5 -47,-52.5
3D body: height 10, standoff 0, extent 0,0 10,10
3D body "WLCSP18.step": height 23.11, standoff -0.01, extent -37,-42.51 37.01,42.52

## WLCSP25 [mil] "STM32 package, WLCSP25, 2.3 x 2.5mm"
pads (25):
  round 9 smd paste+0 mask+0: A1(-31.5,31.5) A2(-15.75,31.5) A3(0,31.5) A4(15.75,31.5) A5(31.5,31.5) B1(-31.5,15.75) B2(-15.75,15.75) B3(0,15.75) B4(15.75,15.75) B5(31.5,15.75) C1(-31.5,0) C2(-15.75,0) C3(0,0) C4(15.75,0) C5(31.5,0) D1(-31.5,-15.75) D2(-15.75,-15.75) D3(0,-15.75) D4(15.75,-15.75) D5(31.5,-15.75) E1(-31.5,-31.5) E2(-15.75,-31.5) E3(0,-31.5) E4(15.75,-31.5) E5(31.5,-31.5)
Top Overlay:
  lines w6: -53.5,-51.5 53.5,-51.5 53.5,51.5 -53.5,51.5 -53.5,-51.5
  text "A" at -98.5,6.5 h50
  text "E" at -98.5,-56.5 h50
  text "1" at -6.5,71.5 h50
  text "5" at 56.5,71.5 h50
Bottom Overlay:
  text "A" at -73.5,6.5 h50
  text "E" at -73.5,-56.5 h50
  text "1" at -56.5,71.5 h50
  text "5" at 6.5,71.5 h50
Keep-Out Layer:
  region: -56.87,-56.87 -56.87,56.87 56.87,56.87 56.87,-56.87
Mechanical 5:
  region: 63.5,-61.5 -63.5,-61.5 -63.5,61.5 63.5,61.5
Mechanical 7:
  lines w1: -98.5,121.5 -48.5,121.5 ; -48.5,0 -48.5,136.5 ; 0,-46.5 213.5,-46.5 ; 0,46.5 213.5,46.5 ; 31.5,15.75 138.5,15.75 ; 31.5,31.5 138.5,31.5 ; 48.5,0 48.5,136.5 ; 98.5,121.5 48.5,121.5 ; 123.5,-34.25 123.5,15.75 ; 123.5,81.5 123.5,31.5 ; 198.5,-96.5 198.5,-46.5 ; 198.5,96.5 198.5,46.5 ; -48.5,121.5 -58.5,126.5 -58.5,116.5 -48.5,121.5 ; 48.5,121.5 58.5,126.5 58.5,116.5 48.5,121.5 ; 123.5,15.75 118.5,5.75 128.5,5.75 123.5,15.75 ; 123.5,31.5 118.5,41.5 128.5,41.5 123.5,31.5 ; 198.5,-46.5 193.5,-56.5 203.5,-56.5 198.5,-46.5 ; 198.5,46.5 193.5,56.5 203.5,56.5 198.5,46.5
  text "Default Padstyle: EX9Y9D0TA" at -337.5,-246.5 h50
  text "0.016in/0.4mm" at 143.5,11.12 h25
  text "0.097in/2.464mm" at -93.75,141.5 h25
  text "0.093in/2.362mm" at 218.5,-12.5 h25
Mechanical 13:
  lines w1: -48.5,38.63 -40.63,46.5 ; -48.5,-46.5 48.5,-46.5 48.5,46.5 -48.5,46.5 -48.5,-46.5
  text "A" at -98.5,6.5 h50
  text "E" at -98.5,-56.5 h50
  text "1" at -6.5,71.5 h50
  text "5" at 56.5,71.5 h50
Mechanical 15:
  region: 58.5,-56.5 -58.5,-56.5 -58.5,56.5 58.5,56.5
  lines w6: -58.5,-56.5 -58.5,56.5 58.5,56.5 58.5,-56.5 -58.5,-56.5
3D body "WLCSP25.step": height 23.11, standoff -0.01, extent -48.5,-46.49 48.51,46.5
